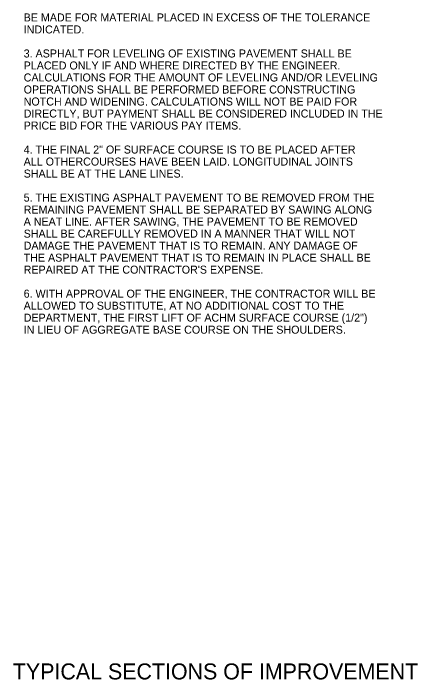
# Model space of a CAD drawing. Extents: x 1955768 to 1955917, y 566446 to 566546.
# Drawn here: x 1955886.19 to 1955916.52, y 566445.68 to 566495.62 of the extents above; entities that cross this region are included whole.
import ezdxf

# ---------------------------------------------------------------- set-up
doc = ezdxf.new("R2010")
doc.units = 0
doc.layers.add('R_Border', color=7, linetype='Continuous')

msp = doc.modelspace()

# ---------------------------------------------------------------- texts
at = {"layer": 'R_Border'}
for s, p in [('BE MADE FOR MATERIAL PLACED IN EXCESS OF THE TOLERANCE', (1955886.97, 566495.009)), ('INDICATED.', (1955886.97, 566494.109)), ('3. ASPHALT FOR LEVELING OF EXISTING PAVEMENT SHALL BE ', (1955886.97, 566492.309)), ('PLACED ONLY IF AND WHERE DIRECTED BY THE ENGINEER.  ', (1955886.97, 566491.409)), ('CALCULATIONS FOR THE AMOUNT OF LEVELING AND/OR LEVELING', (1955886.97, 566490.509)), ('OPERATIONS SHALL BE PERFORMED BEFORE CONSTRUCTING ', (1955886.97, 566489.609)), ('NOTCH AND WIDENING. CALCULATIONS WILL NOT BE PAID FOR ', (1955886.97, 566488.709)), ('DIRECTLY, BUT PAYMENT SHALL BE CONSIDERED INCLUDED IN THE ', (1955886.97, 566487.809)), ('PRICE BID FOR THE VARIOUS PAY ITEMS. ', (1955886.97, 566486.909)), ('4. THE FINAL 2" OF SURFACE COURSE IS TO BE PLACED AFTER', (1955886.97, 566485.109)), ('ALL OTHERCOURSES HAVE BEEN LAID. LONGITUDINAL JOINTS ', (1955886.97, 566484.209)), ('SHALL BE AT THE LANE LINES.', (1955886.97, 566483.309)), ('5. THE EXISTING ASPHALT PAVEMENT TO BE REMOVED FROM THE', (1955886.97, 566481.509)), ('REMAINING PAVEMENT SHALL BE SEPARATED BY SAWING ALONG', (1955886.97, 566480.609)), ('A NEAT LINE. AFTER SAWING, THE PAVEMENT TO BE REMOVED ', (1955886.97, 566479.709)), ('SHALL BE CAREFULLY REMOVED IN A MANNER THAT WILL NOT ', (1955886.97, 566478.809)), ('DAMAGE THE PAVEMENT THAT IS TO REMAIN. ANY DAMAGE OF ', (1955886.97, 566477.909)), ('THE ASPHALT PAVEMENT THAT IS TO REMAIN IN PLACE SHALL BE', (1955886.97, 566477.009)), ("REPAIRED AT THE CONTRACTOR'S EXPENSE.", (1955886.97, 566476.109)), ('6. WITH APPROVAL OF THE ENGINEER, THE CONTRACTOR WILL BE ', (1955886.97, 566474.309)), ('ALLOWED TO SUBSTITUTE, AT NO ADDITIONAL COST TO THE ', (1955886.97, 566473.409)), ('DEPARTMENT, THE FIRST LIFT OF ACHM SURFACE COURSE (1/2") ', (1955886.97, 566472.509)), ('IN LIEU OF AGGREGATE BASE COURSE ON THE SHOULDERS.', (1955886.97, 566471.609))]:
    msp.add_text(s, height=0.6, dxfattribs=at).set_placement(p)
msp.add_text('TYPICAL SECTIONS OF IMPROVEMENT', height=1.2, rotation=0, dxfattribs=at).set_placement((1955886.157, 566445.698))

doc.saveas('drawing.dxf')
